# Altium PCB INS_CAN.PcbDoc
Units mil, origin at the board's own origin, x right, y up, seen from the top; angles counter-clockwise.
Board outline 1181.1 x 1181.1 mil, 2 copper layers (Top Layer, Bottom Layer), stack 62.992 mil thick; 38 components, 30 nets, 142 pads, 128 vias.
Unrouted connection lines stored in the file: 32.
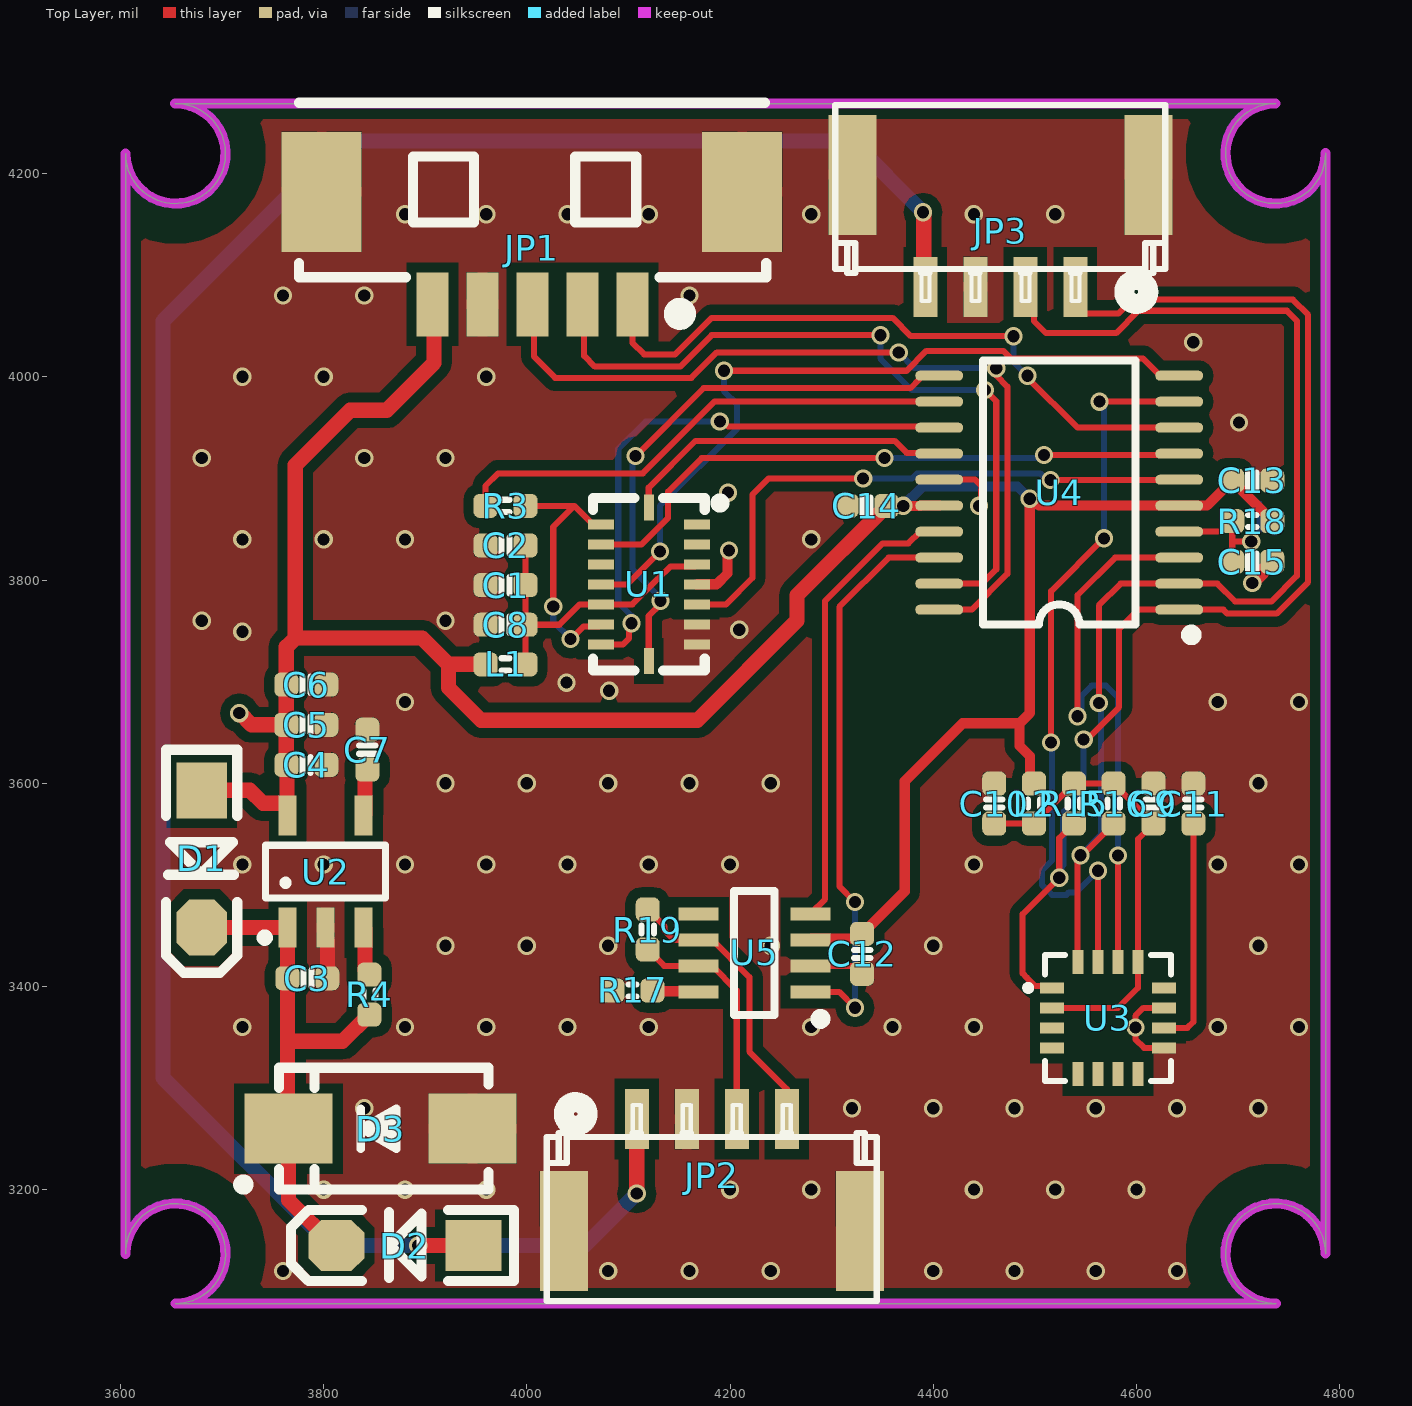
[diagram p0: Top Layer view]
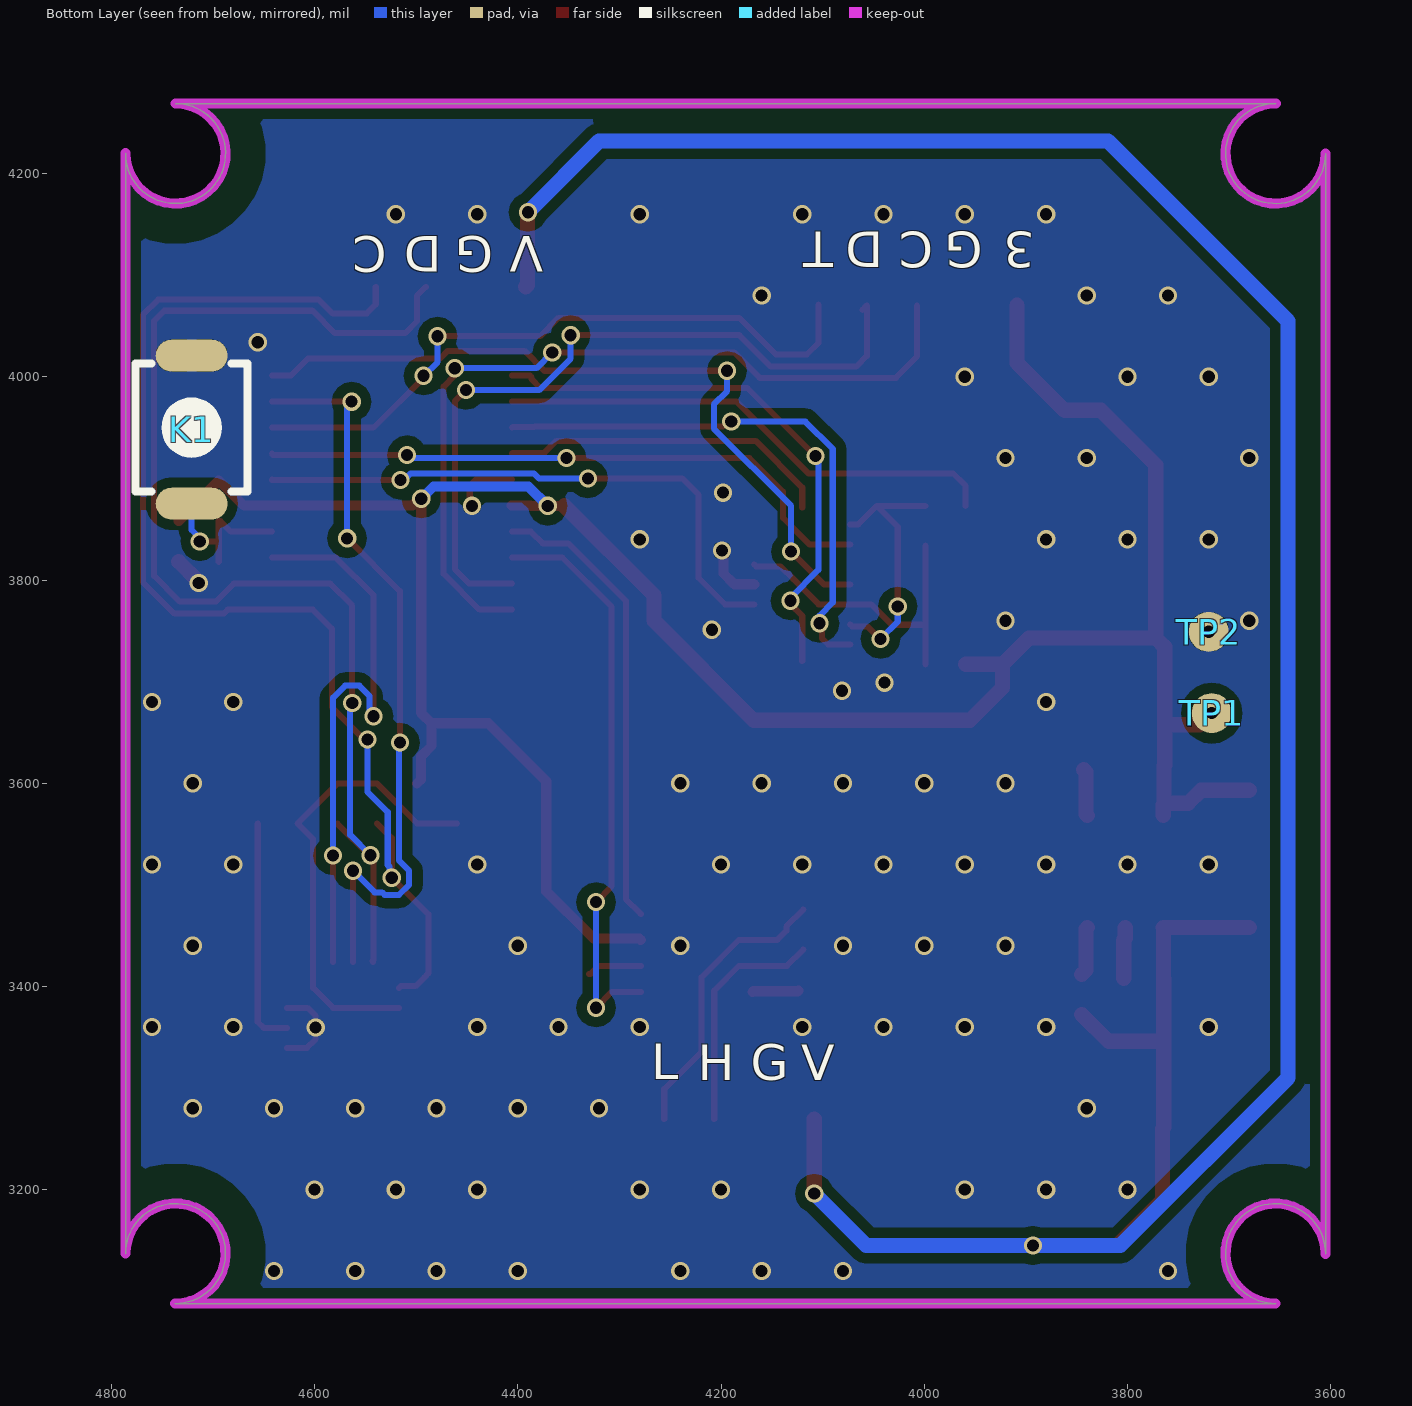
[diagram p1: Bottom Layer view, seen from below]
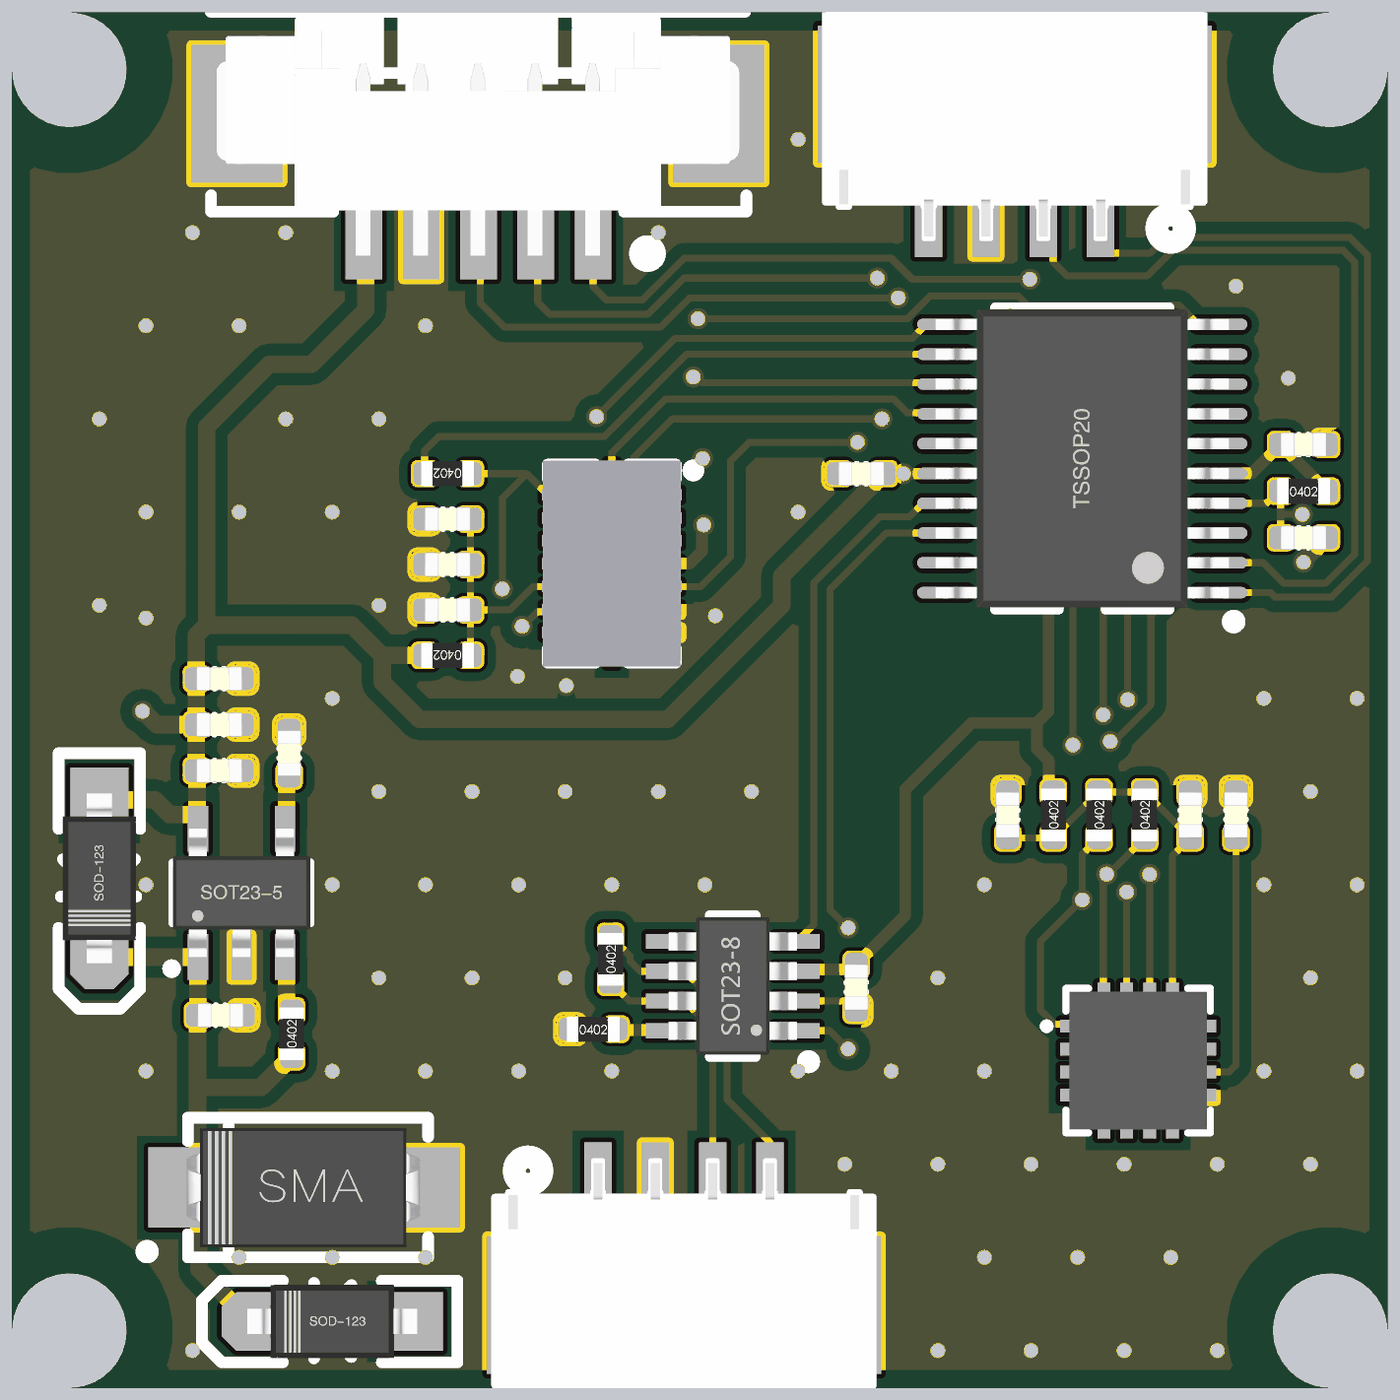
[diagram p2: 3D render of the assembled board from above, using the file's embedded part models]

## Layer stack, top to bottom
Top Solder: solder mask 0.4, Solder Resist, Dk 3.5
Top Layer: signal copper 1.9685
Dielectric 1: dielectric 59.0551, FR-4, Dk 4.8
Bottom Layer: signal copper 1.9685
Bottom Solder: solder mask 0.4, Solder Resist, Dk 3.5

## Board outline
3605,3136.9 3605,4219.79 ccw(c3654.21,4219.79) 3654,4269 4736.89,4269 ccw(c4736.89,4219.79) 4786.1,4220 4786.1,3137.11 ccw(c4736.89,3137.11) 4737.1,3087.9 3654.21,3087.9 ccw(c3654.21,3137.11)

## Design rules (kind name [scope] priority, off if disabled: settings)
AssemblyTestPointUsage [All] p1 off:
AssemblyTestpoint [All] p1 off: testpointundercomponent=TRUE minsize=40 maxsize=100 preferedsize=60 minholesize=0 maxholesize=40 preferedholesize=32 testpointgrid=1 usegrid=TRUE gridtolerance=0.01 allowsidetop=TRUE allowsidebottom=TRUE
Clearance Clearance_1 [InPolygon] p1: gap=10 ignorepadtopadclearanceinfootprint=FALSE
Clearance [All] p2: gap=5 ignorepadtopadclearanceinfootprint=FALSE
ComponentClearance [All] p1 off: gap=10 collisioncheckmode=3 verticalgap=10 showdistances=FALSE
DiffPairsRouting [All] p1 off: maxlimit=10 minlimit=6 mostfreqgap=6 toplayer_minwidth=6 toplayer_maxwidth=15 toplayer_prefwidth=6 bottomlayer_minwidth=6 bottomlayer_maxwidth=15 bottomlayer_prefwidth=6 maxuncoupledlength=500
FabricationTestPointUsage [All] p1 off: valid=0 allowmultiple=FALSE
FabricationTestpoint [All] p1 off: side=3 testpointundercomponent=TRUE minsize=40 maxsize=100 preferedsize=60 minholesize=0 maxholesize=40 preferedholesize=32 testpointgrid=1 allowsidetop=TRUE allowsidebottom=TRUE usegrid=TRUE gridtolerance=0.01
FanoutControl Fanout_BGA [IsBGA] p1 off: bgadir=Out bgaviamode=Centered fanoutstyle=Auto fanoutdirection=Alternating viagrid=1 // Fanout_BGA (Default Rule)
FanoutControl Fanout_LCC [IsLCC] p2 off: bgadir=Out bgaviamode=Centered fanoutstyle=Auto fanoutdirection=Alternating viagrid=1 // Fanout_LCC (Default Rule)
FanoutControl Fanout_SOIC [IsSOIC] p3 off: bgadir=Out bgaviamode=Centered fanoutstyle=Auto fanoutdirection=Alternating viagrid=1 // Fanout_SOIC (Default Rule)
FanoutControl Fanout_Small [(CompPinCount < 5)] p4 off: bgadir=Out bgaviamode=Centered fanoutstyle=Auto fanoutdirection=OutThenIn viagrid=1 // Fanout_Small (Default Rule)
FanoutControl Fanout_Default [All] p5 off: bgadir=Out bgaviamode=Centered fanoutstyle=Auto fanoutdirection=Alternating viagrid=1 // Fanout_Default (Default Rule)
Height [All] p1 off: minheight=0 maxheight=1000 prefheight=500
HoleSize [All] p1 off: absolutevalues=TRUE maxlimit=100 minlimit=1 maxpercent=80.000 minpercent=20.000
HoleToHoleClearance [All] p1 off: gap=10 allowstackedmicrovias=TRUE
LayerPairs [All] p1 off: enforce=TRUE
MinimumSolderMaskSliver [All] p1 off: minsoldermaskwidth=10
NetAntennae [All] p1 off: netantennaetolerance=0
PasteMaskExpansion [All] p1 off: expansion=0
PlaneClearance [All] p1 off: clearance=30
PlaneConnect [All] p1 off: planeconnectstyle=Direct reliefexpansion=10 reliefentries=4 reliefconductorwidth=10 reliefairgap=5
PolygonConnect [All] p1 off: connectstyle=Direct reliefconductorwidth=10 reliefentries=4 polygonreliefangle="90 Angle" airgapwidth=10
RoutingCorners [All] p1 off: cornerstyle=45-Degree minsetback=100 maxsetback=100
RoutingLayers [All] p1 off: top layer_v5=TRUE bottom layer_v5=TRUE
RoutingPriority [All] p1 off: routingpriority=0
RoutingTopology [All] p1 off: topology=Shortest
RoutingVias [All] p1 off: holewidth=10 width=18 viastyle="Through Hole" minholewidth=5 minwidth=5 maxholewidth=100 maxwidth=100
SilkToSilkClearance [All] p1 off: silktosilkclearance=10
SilkToSolderMaskClearance [IsPad] p1 off: minsilkscreentomaskgap=10 clearancetoexposedcopper=TRUE
SolderMaskExpansion [All] p1 off: expansion=4 istentingtop=FALSE
Width [All] p1 off: maxlimit=1000 minlimit=5 preferedwidth=10
4 further rules are at their usual default settings.

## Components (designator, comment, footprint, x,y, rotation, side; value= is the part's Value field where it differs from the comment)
C1 "10uF" C0402 3979,3795 r180 top value=0.1u
C2 "0.1uF" C0402 3979,3834 r180 top value=0.1u
C3 "1uF/25V" C0402 3784,3408 r180 top value=0.1u
C4 "0.1uF/50V" C0402 3783,3618 r180 top value=0.1u
C5 "1uF/25V" C0402 3783,3657.5 r180 top value=0.1u
C6 "0.1uF/50V" C0402 3783,3697 r180 top value=0.1u
C7 "10nF/50V" C0402 3843,3633 r270 top value=0.1u
C8 "0.1uF" C0402 3979,3756 r180 top value=0.1u
C9 "0.1uF" C0402 4616.8,3580 r90 top value=0.1u
C10 "0.1uF" C0402 4460,3580 r90 top value=0.1u
C11 "4.7uF" C0402 4656,3580 r90 top value=0.1u
C12 "0.1uF/50V" C0402 4330,3432 r90 top value=0.1u
C13 "0.1uF" C0402 4714,3898 r0 top value=0.1u
C14 "0.1uF" C0402 4334.31,3873 r180 top value=0.1u
C15 "0.1uF/50V" C0402 4714,3818 r180 top value=0.1u
D1 "1N5819" SOD-123 3680,3525.5 r270 top
D2 "1N5819" SOD-123 3880,3145 r180 top
D3 "SMFJ5.0A" SMA 3856,3260 r180 top
JP1 "HDR-1X5" "MX 1.25-WS-5P" 4005,4182 r180 top
JP2 "SWD" GH1.25-WS-4P 4182,3171 r180 top
JP3 "SWD" GH1.25-WS-4P 4466,4187 r0 top
K1 "6x6x5" SWPBS_SPST_3X2X1 4721,3950 r270 bottom
L1 "60R 25% 3A" R0402 3979,3717 r180 top
L2 "60R 25% 3A" R0402 4499.2,3580 r90 top
R3 "33R" R0402 3979,3873 r180 top value=22R
R4 "100K" R0402 3845,3392 r90 top value=22R
R15 "4.7K" R0402 4538.4,3580 r90 top value=22R
R16 "4.7K" R0402 4577.6,3580 r90 top value=22R
R17 "0R" R0402 4104,3396 r0 top value=22R
R18 "10K" R0402 4714,3858 r0 top value=22R
R19 "120R/NC" R0402 4119,3456 r90 top value=22R
TP1 "TEST" "TEST 1" 3717,3669 r270 bottom
TP2 "TEST" "TEST 1" 3720,3749 r270 bottom
U1 "BMI088" "QFN16 BMI" 4120.04,3795.81 r180 top
U2 "LP5907 3V3" SOT23-5L 3802,3513 r0 top
U3 "IST8310" QFN50_16T_3X3_IST 4572,3369 r270 top
U4 "STM32F042F6P6" TSSOP20_L 4524,3886 r180 top
U5 "MAX3051EKA+T" SOT23-8L 4224,3433 r90 top

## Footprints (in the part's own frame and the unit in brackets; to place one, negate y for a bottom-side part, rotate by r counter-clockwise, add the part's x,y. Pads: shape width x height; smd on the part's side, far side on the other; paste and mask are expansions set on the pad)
C0402 [mm] "CHIP Capacitor, 1.0X0.5mm, 0402"
  rrect50% 0.6x0.6 smd paste-0.05 mask+0.075: 1(-0.5,0) 2(0.5,0)
  silkscreen extent -0.1,-0.2 0.1,0.2, body extent -0.5,-0.26 0.5,0.27, height 0.36
GH1.25-WS-4P [mm] "A1257WR-S-4P"
  rect 1.2x3 smd: 0(-3.7,0.3) 0(3.7,0.3)
  rect 0.6x1.5 smd: 1(1.875,-2.5) 2(0.625,-2.5) 3(-0.625,-2.5) 4(-1.875,-2.5)
  silkscreen extent -4.13,-2.93 4.12,2.05, body extent -4.12,-2.8 4.12,2.1, height 4.4
"MX 1.25-WS-5P" [mm] "长：11.4mm，宽：4.2mm，高：3.4mm"
  rect 2x3 smd: 0(-5.257,0) 0(5.257,0)
  rect 0.8x1.6 smd: 1(-2.514,2.811) 2(-1.264,2.811) 3(-0.014,2.811) 4(1.236,2.811) 5(2.486,2.811)
  silkscreen extent -5.86,-2.23 5.83,3.25, body extent -5.7,-2.1 5.7,3.09, height 3.4
"QFN16 BMI" [mm] "16脚，长x宽x高：4x4x0.8mm，脚距：0.65mm"
  rect 0.65x0.25 smd: 1(-1.2,-1.498) 2(-1.2,-0.998) 3(-1.2,-0.498) 4(-1.2,0.002) 5(-1.2,0.502) 6(-1.2,1.002) 7(-1.2,1.502) 9(1.2,1.502) 10(1.2,1.002) 11(1.2,0.502) 12(1.2,0.002) 13(1.2,-0.498) 14(1.2,-0.998) 15(1.2,-1.498)
  rect 0.25x0.65 smd: 8(0,1.915) 16(0,-1.915)
  silkscreen extent -1.89,-2.16 1.4,2.16, body extent -1.5,-2.25 1.5,2.25, height 0.88
QFN50_16T_3X3_IST [mm] "RGT PVQFN (TI), 16-lead, pitch: 0.5mm, 3x3mm"
  rect 0.28x0.6 smd: 1(-0.75,-1.4) 2(-0.25,-1.4) 3(0.25,-1.4) 4(0.75,-1.4) 9(0.75,1.4) 10(0.25,1.4) 11(-0.25,1.4) 12(-0.75,1.4)
  rect 0.6x0.28 smd: 5(1.4,-0.75) 6(1.4,-0.25) 7(1.4,0.25) 8(1.4,0.75) 13(-1.4,0.75) 14(-1.4,0.25) 15(-1.4,-0.25) 16(-1.4,-0.75)
  silkscreen extent -1.58,-2.07 1.58,1.58, body extent -1.5,-1.5 1.5,1.5, height 1
R0402 [mm] "CHIP Resistor, 1.0X0.5mm, 0402"
  rrect50% 0.6x0.6 smd paste-0.05 mask+0.075: 1(-0.5,0) 2(0.5,0)
  silkscreen extent -0.1,-0.15 0.1,0.15, body extent -0.57,-0.27 0.58,0.28, height 0.41
SMA [mm] "4.5x2.6*2.2mm（长宽高，不包括引脚）"
  rect 2.2x1.75 smd: 1(-2.3,0) 2(2.3,0)
  silkscreen extent -2.7,-1.52 3.56,1.52, body extent -2.53,-1.3 2.58,1.3, height 2.15
SOD-123 [mil] "2.7x1.6X1.1mm（长宽高，不包括引脚）"
  rect 55x50 smd: 1(-67.5,0)
  oct 55x50 smd: 2(67.5,0)
  silkscreen extent -108,-35 112,35, body extent -73,-31 73,31, height 48
SOT23-5L [mm] "3x1.6x1.1mm(长宽高)"
  rect 0.45x1 smd: 1(-0.95,-1.4) 2(0,-1.4) 3(0.95,-1.4) 4(0.95,1.4) 5(-0.95,1.4)
  silkscreen extent -1.6,-1.73 1.5,0.66, body extent -1.5,-1.4 1.5,1.4, height 1.15
SOT23-8L [mm] "3x1.6x1.1mm(长宽高)"
  rect 0.325x1 smd: 1(-0.975,-1.397) 2(-0.325,-1.397) 3(0.325,-1.397) 4(0.975,-1.397) 5(0.975,1.397) 6(0.325,1.397) 7(-0.325,1.397) 8(-0.975,1.397)
  silkscreen extent -1.77,-1.78 1.55,0.51, body extent -1.5,-1.4 1.5,1.4, height 1.15
SWPBS_SPST_3X2X1 [mm] "SWITCH, PUSHBUTTON, SMD, SPST, 3X2.5mm"
  oval 0.8x1.8 smd mask+0.1: 1(-1.8,0) 2(1.9,0)
  silkscreen extent -1.6,-1.4 1.6,1.4, body extent -2,-1.25 2,1.25, height 1.6
"TEST 1" [mm] "测试点1mm"
  round 1 smd paste-1: 1(0,0)
TSSOP20_L [mm] "6.5*6.4*1（长宽高）"
  oval 1.2x0.25 smd: 1(-3,2.925) 2(-3,2.275) 3(-3,1.625) 4(-3,0.975) 5(-3,0.325) 6(-3,-0.325) 7(-3,-0.975) 8(-3,-1.625) 9(-3,-2.275) 10(-3,-2.925) 11(3,-2.925) 12(3,-2.275) 13(3,-1.625) 14(3,-0.975) 15(3,-0.325) 16(3,0.325) 17(3,0.975) 18(3,1.625) 19(3,2.275) 20(3,2.925)
  silkscreen extent -3.43,-3.3 1.91,3.69, body extent -3.2,-3.25 3.2,3.25, height 1.03

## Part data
C1 C2 C3 C4 C5 C6 C7 C8 C9 C10 C11 C12 C13 C14 C15: library part 电容-0402, "Capacitor"
D1 D2: library part Diode_SMA, "Diode"
D3: library part SMBJ28CA
JP1: library part "Header 5", "5P接插件"
JP2 JP3: library part "Header 1*4"
K1: library part "TSW DIP-6x6_V", "侧按直插6x6轻触开关"
L1 L2: library part L, "小功率贴片电感"
R3 R4 R15 R16 R17 R18 R19: library part 电阻-0402, "Resistor"
TP1 TP2: "测试点"
U1: BOM_JLCPCB Part Class="Extended Part", BOM_Manufacturer="Bosch Sensortec"
U2: library part LP2992, "LDO"
U4: "CPU内核:ARM Cortex-M0;CPU最大主频:48MHz;工作电压范围:1.65V~3.6V;程序存储容量:32KB;程序存储器类型:FLASH;RAM总容量:6KB;GPIO端口数量:16;", JLCPCB Part Class=扩展库, Low-Voltage Detect=有, Manufacturer=ST(意法半导体), Operating Temperature Range=-40℃~+85℃, Operating Voltage Range=1.65V~3.6V
U5: BOM_JLCPCB Part Class="Extended Part", BOM_Manufacturer=MAXIM

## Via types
v1: diameter 18, hole 12, Top Layer to Bottom Layer, tented both sides, 128 vias

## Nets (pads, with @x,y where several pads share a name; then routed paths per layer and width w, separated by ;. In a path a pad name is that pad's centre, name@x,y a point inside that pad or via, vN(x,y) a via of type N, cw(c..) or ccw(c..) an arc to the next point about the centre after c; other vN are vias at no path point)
3V3: C4.2 C5.2 C6.2 C12.2 C13.1 C14.1 D1.1 JP1.5 L1.2 L2.2 R18.2 TP1.1 U2.5 U4.5 U4.16 U5.3 | length 2598
  Top Layer w10: U5.3 4280.4,3447.19 4325.51,3447.19 C12.2 4372,3493.68 4372,3602 4429,3659 4485,3659 ; C14.1 v1(4370.57,3873) 4387.14,3873 4387.35,3873.2 U4.16 ; L2.2 4495.19,3603.69 4495.19,3626.5 4485,3636.69 4485,3659 ; R18.2 4733.69,3858.32 4694.31,3897.69 C13.1 4669.6,3873.28 4642.19,3873.28 U4.5 4503.96,3873.2 4497.16,3880 v1(4495,3880) 4495,3669 4485,3659
  Top Layer w15: D1.1 3727.5,3593 3740.2,3580.3 3763.24,3580.3 U2.5@3763.96,3579.59 ; v1(3717,3669) 3717.5,3669 3729,3657.5 C5.2 ; U2.5 3764.6,3578.94 U2.5@3763.96,3579.59 ; JP1.5@3908.72,4070.35 3908.72,4013.72 3862,3967 3826,3967 3772.1,3913.1 3772.1,3743 ; L1.2 3923,3717 ; C14.1 4266,3785 4266,3760 4168,3662 3955,3662 3923,3694 3923,3717 ; C5.2 C6.2 3763.32,3734.21 3772.1,3743 ; C5.2 C4.2 3763.96,3617.36 U2.5@3763.96,3579.59 ; 3772.1,3743 3897,3743 3923,3717
  Bottom Layer w10: v1(4370.57,3873) 4389.57,3892 4483,3892 v1(4495,3880)
5V: C3.2 D1.2 D2.2 D3.2 R4.1 U2.1 | length 511.1
  Top Layer w15: D1.2 3680.06,3457.94 3764.54,3457.94 U2.1 3764.46,3457.74 3764.46,3408.14 C3.2 3764.32,3347 ; D2.2 3810,3145 3765.45,3189.55 D3.2 3764.32,3261.13 3764.32,3347 ; R4.1 3818.68,3346 3765.32,3346 3764.32,3347
CAN_D: U4.18 U5.1 | length 569.8
  Top Layer w6: U5.1 4307.39,3394.61 v1(4323,3379) ; v1(4323,3483) 4307.61,3498.39 4307.61,3773.61 4356.02,3822.02 U4.18
  Bottom Layer w6: v1(4323,3379) v1(4323,3483)
CAN_H: JP2.3 R19.1 U5.7 | length 230.8
  Top Layer w6: R19.1 4135.11,3420.2 U5.7 4182.29,3420.2 4206.61,3395.89 JP2.3
CAN_L: JP2.4 R19.2 U5.6 | length 285.1
  Top Layer w6: R19.2 4135.66,3459.03 4135.66,3454.65 4144.51,3445.8 U5.6 4182.29,3445.8 4219.05,3409.03 4219.05,3335.77 4255.82,3299 JP2.4
CAN_R: U4.17 U5.4 | length 454.6
  Top Layer w6: U5.4 4293.63,3486.02 4293.63,3779.4 4350.23,3836 4375.57,3836 4387.19,3847.61 U4.17
GND: C1.2 C2.2 C3.1 C4.1 C5.1 C6.1 C7.1 C8.2 C9.2 C10.2 C11.2 C12.1 C13.2 C14.2 C15.1 D3.1 JP1.0 JP1.4 JP2.0 JP2.2 JP3.0 JP3.3 K1.1 R17.1 TP2.1 U1.4 U1.6 U1.7 U2.2 U3.9 U3.11 U4.15 U5.2 | length 343.8
  Top Layer w6: U5.2 4320.54,3420.2 4328.43,3412.32 C12.1 ; U4.15 4441.2,3898.8 4449,3891 4447.3,3889.3 4447.3,3875.3 v1(4445,3873) ; U3.9 4607.53,3339.47 4599,3348 4599,3371 4606.84,3378.84 U3.11
  Top Layer w10: U1.4 4167.35,3795.81 4186.81,3795.81 4197.47,3806.47 4197.47,3827.47 v1(4199,3829)
  Top Layer w15: U2.2 3802,3447.06 3803.68,3445.37 C3.1 ; v1(4714,3797) 4714.57,3797.57 4714.57,3798.89 C15.1
  other v1: 3760,3120 4080,3120 4160,3120 4240,3120 4400,3120 4480,3120 4560,3120 4640,3120 3800,3200 3880,3200 3960,3200 4200,3200 4280,3200 4440,3200 4520,3200 4600,3200 3840,3280 4320,3280 4400,3280 4480,3280 4560,3280 4640,3280 4720,3280 3720,3360 3880,3360 3960,3360 4040,3360 4120,3360 4280,3360 4360,3360 4440,3360 4599,3359.5 4680,3360 4760,3360 3920,3440 4000,3440 4080,3440 4240,3440 4400,3440 4720,3440 3720,3520 3800,3520 3880,3520 3960,3520 4040,3520 4120,3520 4200,3520 4440,3520 4680,3520 4760,3520 3920,3600 4000,3600 4080,3600 4160,3600 4240,3600 4720,3600 3880,3680 4680,3680 4760,3680 4081,3691 4039,3699 3720,3749 4209,3751 3680,3760 3920,3760 3720,3840 3800,3840 3880,3840 4280,3840 4198,3886 3680,3920 3840,3920 3920,3920 4701,3955 3720,4000 3800,4000 3960,4000 4656,4034 3760,4080 3840,4080 4160,4080 3880,4160 3960,4160 4040,4160 4120,4160 4280,4160 4440,4160 4520,4160
IMU_CS1_Accel: U1.14 U4.7 | length 621.4
  Top Layer w6: U1.14 4112.97,3835.1 4138.98,3861.12 4138.98,3886.98 4172,3920 v1(4352,3920) ; v1(4509,3923) 4640.72,3923 U4.7
  Bottom Layer w6: v1(4352,3920) 4506,3920 v1(4509,3923)
IMU_CS1_Gyro: U1.5 U4.6 | length 579.2
  Top Layer w6: U1.5 4196.05,3776.05 4222,3802 4222,3884 4238,3900 v1(4331,3900) ; v1(4515.4,3898.4) 4641.71,3898.4 U4.6
  Bottom Layer w6: v1(4331,3900) 4379.19,3900 4384.19,3905 4505.55,3905 4512.15,3898.4 v1(4515.4,3898.4)
IMU_INT1_Accel: U1.16 U4.14 | length 329.9
  Top Layer w6: U1.16 4120.04,3891.04 4166,3937 4362.04,3937 4373.92,3925.12 4405.15,3925.12 U4.14
IMU_INT1_Gyro: U1.12 U4.10 | length 752.7
  Top Layer w6: U1.12 4098.73,3795.73 v1(4131,3828) ; v1(4194,4006) 4373.76,4006 4393.28,4025.53 4469.04,4025.53 4476.57,4018 4606.57,4018 4623.41,4001.16 U4.10
  Bottom Layer w6: v1(4131,3828) 4131,3872.96 4207,3948.96 4207,3972.96 4194,3985.96 v1(4194,4006)
IMU_MISO: R3.2 U4.12 | length 500.6
  Top Layer w6: R3.2 3959.32,3892.66 3971.66,3905 4114.04,3905 4184.61,3975.57 U4.12
IMU_MOSI: U1.9 U4.13 | length 552.6
  Top Layer w6: U1.9 4094.67,3736.67 4100.7,3742.7 4100.7,3755.2 v1(4103,3757.5) ; v1(4190,3956) 4193.25,3956 4198.25,3951 4383.45,3951 4383.74,3950.71 4405.15,3950.71 U4.13
  Bottom Layer w6: v1(4103,3757.5) 4103,3765 4090,3778 4090,3929.04 4116.96,3956 v1(4190,3956)
IMU_SCK: U1.8 U4.11 | length 551.6
  Top Layer w6: v1(4107,3922) 4174,3989 4377.75,3989 4386.45,3997.7 4386.45,3999.38 4388.23,4001.16 U4.11 ; U1.8 4120,3720.46 4120,3764.75 4127,3771.75 4127,3771.84 4131.51,3776.35 v1(4131.51,3779.6)
  Bottom Layer w6: v1(4107,3922) 4104.1,3919.1 4104.1,3809.9 4131.51,3782.49 v1(4131.51,3779.6)
IST_DRDY: U3.15 U4.9 | length 741
  Top Layer w6: v1(4515.98,3640.02) 4515.98,3788.98 v1(4568,3841) ; U3.15 v1(4562.16,3513.84) ; v1(4563.57,3975.57) U4.9
  Bottom Layer w6: v1(4515.98,3640.02) 4517,3639 4517,3524.04 4507,3514.04 4507,3499.96 4516.96,3490 4531.04,3490 4533.53,3492.49 4540.81,3492.49 v1(4562.16,3513.84) ; v1(4563.57,3975.57) 4568,3971.13 v1(4568,3841)
IST_RSTN: U3.14 U4.3 | length 561.1
  Top Layer w6: v1(4542,3666) 4542,3785 4579.02,3822.02 U4.3 ; U3.14 v1(4581.84,3528.84)
  Bottom Layer w6: v1(4542,3666) 4546,3670 4546,3686.04 4555.96,3696 4570.04,3696 4581.84,3684.2 v1(4581.84,3528.84)
IST_SCL: JP3.1 R15.1 U3.1 U4.1 | length 1207.4
  Top Layer w6: U3.1 4515.06,3400.35 4500.65,3400.35 4492.24,3408.76 4488,3413 4488,3471 v1(4524,3507) 4524,3545.91 R15.1 ; JP3.1 4539.82,4071.3 4548.63,4062.49 4582.51,4062.49 4596.03,4076 4753.97,4076 4769,4060.97 4769,3798.03 4737.97,3767 4689.35,3767 4685.5,3770.84 U4.1 4601.84,3770.84 4583,3752 4583,3674.96 4551.04,3643 v1(4548,3643)
  Bottom Layer w6: v1(4524,3507) 4526.3,3509.3 4526.3,3517.78 4528,3519.49 4528,3571.65 4548,3591.65 v1(4548,3643)
IST_SDA: JP3.2 R16.1 U3.16 U4.2 | length 1196.2
  Top Layer w6: JP3.2 4499.05,4080.13 4499.05,4054.95 4511,4043 4580,4043 4602,4065 4748,4065 4758,4055 4758,3804 4733,3779 4697,3779 4679.57,3796.43 U4.2 4584.43,3796.43 4563,3775 v1(4563,3679) ; U3.16 4543.14,3424.79 4542,3425.93 4542,3524.72 v1@4544.28,3527 ; v1@4543.28,3528 v1@4544.28,3527 ; v1(4545,3529.15) v1@4545,3527.72 ; R16.1 v1@4545,3527.72 ; v1@4544.28,3527 v1@4545,3527.72
  Bottom Layer w6: v1(4545,3529.15) 4565,3549.15 4565,3677 v1(4563,3679)
NetC1_1: C1.1 C2.1 C8.1 L1.1 U1.3 U1.11 | length 310.2
  Top Layer w6: L1.1 C8.1 ; C2.1 C1.1 C8.1 ; U1.3 4165.35,3813.49 4141.49,3813.49 4129.1,3801.1 4128.97,3801.1 4103.92,3776.05 U1.11 4052.1,3776.05 4032.04,3756 C8.1
NetC7_2: C7.2 U2.4 | length 46.7
  Top Layer w15: U2.4 3840.76,3569.48 3840.76,3611.07 C7.2
NetC9_1: C9.1 C10.1 L2.1 R15.2 R16.2 U3.2 U3.13 | length 450.5
  Top Layer w6: C10.1 L2.1 4499.2,3560.4 4538.4,3599.6 R15.2 R16.2 4577.6,3599.6 4616.8,3560.4 C9.1 4601.53,3545.04 U3.13 4601.53,3398.53 4581.84,3378.84 U3.2
NetC11_1: C11.1 U3.10 | length 226.6
  Top Layer w6: U3.10 4650.16,3359.16 4656,3365 C11.1
NetR3_1: R3.1 U1.10 U1.15 | length 264
  Top Layer w6: R3.1 4046.71,3873 ; v1(4026,3774) 4026,3852.29 4046.71,3873 ; v1(4043,3742) 4043.57,3742 4056.01,3754.44 4070.87,3754.44 U1.10 ; U1.15 4064.92,3854.78 4046.71,3873
  Bottom Layer w6: v1(4026,3774) 4026,3759 v1(4043,3742)
NetR4_2: R4.2 U2.3 | length 48.5
  Top Layer w15: U2.3 3840.76,3456.52 3840.76,3415.93 R4.2
NetR17_2: R17.2 U5.8 | length 45.9
  Top Layer w10: R17.2 4124.38,3395.31 4168.31,3395.31 U5.8
NRST: C15.2 K1.2 R18.1 U4.4 | length 155.7
  Top Layer w6: U4.4 4682.36,3847.61 4692.74,3858 R18.1 4694.31,3838 ; C15.2 4694.31,3838 ; v1(4713,3838) 4694.31,3838
  Bottom Layer w6: v1(4713,3838) 4713,3841.25 4721,3849.25 K1.2
SWCLK: JP1.3 U4.20 | length 819.5
  Top Layer w6: JP1.3@4007.15,4070.35 4007.15,4019.85 4028,3999 4162,3999 4187,4024 v1(4366,4024) ; U4.20 4437.88,3770.84 4473,3805.96 4473,3990.43 4462,4001.43 v1(4462,4008.53)
  Bottom Layer w6: v1(4366,4024) 4381.47,4008.53 v1(4462,4008.53)
SWDIO: JP1.2 U4.19 | length 746.6
  Top Layer w6: JP1.2@4060.71,4066 4056.36,4070.35 4056.36,4020.64 4067,4010 4151,4010 4182,4041 v1(4348,4041) ; U4.19 4447.92,3796.43 4462,3810.51 4462,3976 v1(4451,3987)
  Bottom Layer w6: v1(4348,4041) 4348,4017.96 4378.96,3987 v1(4451,3987)
UART2_Tx: JP1.1 U4.8 | length 657.3
  Top Layer w6: JP1.1 4103.97,4033.39 4115.36,4022 4146,4022 4182,4058 4360,4058 4378,4040 4477,4040 4478,4039 v1(4479,4040) ; v1(4492.72,4001) 4492.72,3999.28 4542.02,3949.98 U4.8
  Bottom Layer w6: v1(4479,4040) 4479,4014.46 4492.46,4001 v1(4492.72,4001)
VCC: D2.1 JP2.1 JP3.4 | length 2353.1
  Top Layer w15: v1(3893,3145) D2.1 ; v1(4108.18,3196.18) JP2.1 ; v1(4390,4162) 4390.57,4161.43 4390.57,4090.18 JP3.4
  Bottom Layer w15: v1(4108.18,3196.18) 4057,3145 v1(3893,3145) 3807,3145 3642,3310 3642,4055 3819,4232 4320,4232 v1(4390,4162)
pads on no net: U1.1 U1.2 U1.13 U3.3 U3.4 U3.5 U3.6 U3.7 U3.8 U3.12 U5.5

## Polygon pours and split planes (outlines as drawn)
GND on Top Layer "GND_L01_P000" (solid, remove dead copper, pour order 0): 3605,3136.9 3605,4219.79 ccw(c3654.21,4219.79) 3654,4269 4736.89,4269 ccw(c4736.89,4219.79) 4786.1,4220 4786.1,3137.11 ccw(c4736.89,3137.11) 4737.1,3087.9 3654.21,3087.9 ccw(c3654.21,3137.11)
GND on Bottom Layer "GND_L02_P001" (solid, remove dead copper, pour order 1): 3605,3136.9 3605,4219.79 ccw(c3654.21,4219.79) 3654,4269 4736.89,4269 ccw(c4736.89,4219.79) 4786.1,4220 4786.1,3137.11 ccw(c4736.89,3137.11) 4737.1,3087.9 3654.21,3087.9 ccw(c3654.21,3137.11)

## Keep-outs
Keep-Out Layer:
  the board outline again, w10

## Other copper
Top Layer:
  pour cut-out: 4648.31,3137.11 ccw(c4736.89,3137.11) 4736.89,3048.53 ccw(c4736.89,3137.11) 4825.47,3137.11 ccw(c4736.89,3137.11) 4736.89,3225.69 ccw(c4736.89,3137.11)
  pour cut-out: 3565.63,3137.11 ccw(c3654.21,3137.11) 3654.21,3048.53 ccw(c3654.21,3137.11) 3742.8,3137.11 ccw(c3654.21,3137.11) 3654.21,3225.69 ccw(c3654.21,3137.11)
  pour cut-out: 4648.31,4219.79 ccw(c4736.89,4219.79) 4736.89,4131.2 ccw(c4736.89,4219.79) 4825.47,4219.79 ccw(c4736.89,4219.79) 4736.89,4308.37 ccw(c4736.89,4219.79)
  pour cut-out: 3654.21,4131.2 cw(c3654.21,4219.79) 3565.63,4219.79 cw(c3654.21,4219.79) 3654.21,4308.37 cw(c3654.21,4219.79) 3742.8,4219.79 cw(c3654.21,4219.79)
Bottom Layer:
  pour cut-out: 3654.21,4131.2 cw(c3654.21,4219.79) 3565.63,4219.79 cw(c3654.21,4219.79) 3654.21,4308.37 cw(c3654.21,4219.79) 3742.8,4219.79 cw(c3654.21,4219.79)
  pour cut-out: 4648.31,4219.79 ccw(c4736.89,4219.79) 4736.89,4131.2 ccw(c4736.89,4219.79) 4825.47,4219.79 ccw(c4736.89,4219.79) 4736.89,4308.37 ccw(c4736.89,4219.79)
  pour cut-out: 4648.31,3137.11 ccw(c4736.89,3137.11) 4736.89,3048.53 ccw(c4736.89,3137.11) 4825.47,3137.11 ccw(c4736.89,3137.11) 4736.89,3225.69 ccw(c4736.89,3137.11)
  pour cut-out: 3565.63,3137.11 ccw(c3654.21,3137.11) 3654.21,3048.53 ccw(c3654.21,3137.11) 3742.8,3137.11 ccw(c3654.21,3137.11) 3654.21,3225.69 ccw(c3654.21,3137.11)

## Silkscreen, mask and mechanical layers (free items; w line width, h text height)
Bottom Overlay:
  text "3" at 3891.15,4154.39 h60 r180
  text "G" at 3942.15,4154.39 h60 r180
  text "C" at 3991.15,4154.39 h60 r180
  text "D" at 4040.07,4154.39 h60 r180
  text "T" at 4118.93,4154.39 h60 r180
  text "V" at 4375.19,4150.39 h60 r180
  text "G" at 4424.19,4150.39 h60 r180
  text "D" at 4475.07,4150.39 h60 r180
  text "C" at 4529.07,4150.39 h60 r180
  text "L" at 4268.58,3296.73 h60
  text "V" at 4120.81,3295.61 h60
  text "G" at 4170.81,3295.61 h60
  text "H" at 4222.85,3295.61 h60
Mechanical 15:
  circle w10: c4572,3368 r157.48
